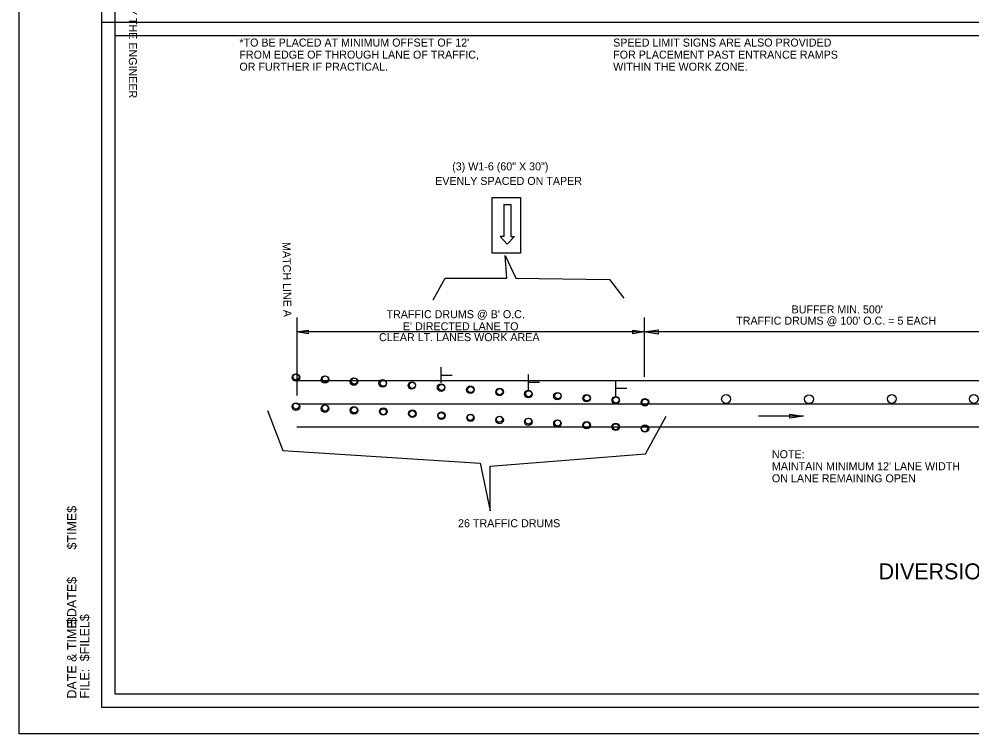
# Model space of a CAD drawing. Extents: x -500 to 213, y 382723 to 382830.
# Drawn here: x -316.3 to -244.8, y 382723.1 to 382776.7 of the extents above; entities that cross this region are included whole.
import ezdxf

# ---------------------------------------------------------------- set-up
doc = ezdxf.new("R2010")
doc.units = 0
for name, color, linetype in [('Default', 7, 'Continuous'), ('R_Border', 7, 'Continuous'), ('R_Border Notes', 7, 'Continuous'), ('R_Border Plan-Plan', 7, 'Continuous'), ('R_No Plot', 7, 'Continuous')]:
    doc.layers.add(name, color=color, linetype=linetype)

msp = doc.modelspace()

# ---------------------------------------------------------------- linework, layer by layer
at = {"layer": 'Default'}
for p, q in [((-279.942, 382762.819), (-279.942, 382760.429)), ((-279.942, 382762.819), (-279.41, 382762.819)), ((-279.41, 382762.819), (-279.41, 382760.429)), ((-279.942, 382760.429), (-280.208, 382760.429)), ((-280.208, 382760.429), (-279.676, 382759.846)), ((-279.676, 382759.846), (-279.144, 382760.429)), ((-279.41, 382760.429), (-279.144, 382760.429)), ((-295.463, 382754.338), (-295.463, 382748.51)), ((-269.405, 382754.338), (-269.405, 382749.91)), ((-295.482, 382753.26), (-294.613, 382753.39)), ((-269.405, 382753.26), (-295.482, 382753.26)), ((-294.613, 382753.129), (-295.482, 382753.26)), ((-295.463, 382752.815), (-295.463, 382748.51)), ((-294.613, 382753.39), (-294.613, 382753.129)), ((-270.274, 382753.129), (-270.274, 382753.39)), ((-270.274, 382753.39), (-269.405, 382753.26)), ((-269.405, 382753.26), (-270.274, 382753.129)), ((-269.405, 382753.26), (-268.374, 382753.414)), ((-238.494, 382753.26), (-269.405, 382753.26)), ((-268.374, 382753.105), (-269.405, 382753.26)), ((-268.374, 382753.414), (-268.374, 382753.105)), ((-284.623, 382749.452), (-284.623, 382750.614)), ((-284.606, 382750.03), (-283.813, 382750.03)), ((-278.082, 382748.911), (-278.082, 382750.072)), ((-295.463, 382749.623), (-268.558, 382749.623)), ((-278.065, 382749.488), (-277.272, 382749.488)), ((-271.525, 382748.459), (-271.525, 382749.621)), ((-269.385, 382749.623), (-242.492, 382749.623)), ((-271.508, 382749.037), (-270.716, 382749.037)), ((-295.463, 382747.884), (-268.181, 382747.884)), ((-269.475, 382747.884), (-242.275, 382747.884)), ((-258.486, 382746.796), (-258.486, 382747.105)), ((-258.486, 382747.105), (-257.456, 382746.951)), ((-257.456, 382746.951), (-260.835, 382746.951)), ((-257.456, 382746.951), (-258.486, 382746.796)), ((-295.463, 382746.146), (-267.839, 382746.146)), ((-269.426, 382746.146), (-241.92, 382746.146))]:
    msp.add_line(p, q, dxfattribs=at)
msp.add_lwpolyline([(-280.818, 382759.163), (-280.818, 382763.354), (-278.675, 382763.354), (-278.675, 382759.163)], close=True, dxfattribs=at)
for points in [[(-285.228, 382755.677), (-284.327, 382757.307), (-279.704, 382757.307), (-279.824, 382758.995), (-279.043, 382757.307), (-272.019, 382757.191), (-270.938, 382755.793)], [(-297.643, 382747.372), (-296.516, 382744.381), (-281.706, 382743.433), (-280.954, 382739.858), (-280.954, 382743.214), (-269.305, 382744.117), (-267.751, 382746.951)]]:
    msp.add_lwpolyline(points, dxfattribs=at)
for centre, radius in [((-295.522, 382749.848), 0.281), ((-295.521, 382749.894), 0.229), ((-295.509, 382749.893), 0.229), ((-293.348, 382749.696), 0.281), ((-293.328, 382749.735), 0.229), ((-291.175, 382749.543), 0.281), ((-291.148, 382749.578), 0.229), ((-289.027, 382749.406), 0.281), ((-288.967, 382749.42), 0.229), ((-286.833, 382749.247), 0.281), ((-286.786, 382749.262), 0.229), ((-284.639, 382749.088), 0.281), ((-284.606, 382749.105), 0.229), ((-282.445, 382748.929), 0.281), ((-282.425, 382748.947), 0.229), ((-280.251, 382748.769), 0.281), ((-280.244, 382748.79), 0.229), ((-278.103, 382748.604), 0.281), ((-278.064, 382748.632), 0.229), ((-275.916, 382748.452), 0.281), ((-275.883, 382748.475), 0.229), ((-273.729, 382748.299), 0.281), ((-273.702, 382748.317), 0.229), ((-271.542, 382748.147), 0.281), ((-263.269, 382748.237), 0.333), ((-257.055, 382748.222), 0.333), ((-250.841, 382748.243), 0.333), ((-244.693, 382748.245), 0.333), ((-295.522, 382747.659), 0.281), ((-295.521, 382747.704), 0.229), ((-295.509, 382747.703), 0.229), ((-293.348, 382747.521), 0.281), ((-293.331, 382747.562), 0.229), ((-271.522, 382748.159), 0.229), ((-269.355, 382747.995), 0.281), ((-269.353, 382748.003), 0.229), ((-269.341, 382748.002), 0.229), ((-291.175, 382747.382), 0.281), ((-291.153, 382747.421), 0.229), ((-288.972, 382747.301), 0.281), ((-288.976, 382747.28), 0.229), ((-286.792, 382747.142), 0.281), ((-286.798, 382747.139), 0.229), ((-284.611, 382746.982), 0.281), ((-284.62, 382746.999), 0.229), ((-282.431, 382746.823), 0.281), ((-282.442, 382746.858), 0.229), ((-280.251, 382746.664), 0.281), ((-280.264, 382746.717), 0.229), ((-278.103, 382746.526), 0.281), ((-278.087, 382746.576), 0.229), ((-275.916, 382746.402), 0.281), ((-275.909, 382746.435), 0.229), ((-273.729, 382746.277), 0.281), ((-273.731, 382746.294), 0.229), ((-271.542, 382746.152), 0.281), ((-271.553, 382746.153), 0.229), ((-269.355, 382746.028), 0.281), ((-269.388, 382746.013), 0.229), ((-269.375, 382746.012), 0.229)]:
    msp.add_circle(centre, radius, dxfattribs=at)
at = {"layer": 'R_Border'}
for p, q in [((-310.08, 382725.12), (-310.08, 382827.85)), ((-310.08, 382725.12), (-310.08, 382725.12)), ((-151.99, 382725.12), (-310.08, 382725.12))]:
    msp.add_line(p, q, dxfattribs=at)
at = {"layer": 'R_Border Plan-Plan'}
msp.add_line((-310.08, 382776.485), (-151.99, 382776.485), dxfattribs=at)
at = {"layer": 'R_No Plot'}
for points in [[(-316.283, 382829.798), (-149.613, 382829.798), (-149.613, 382723.129), (-316.283, 382723.129)], [(-309.08, 382826.85), (-184.31, 382826.85), (-184.31, 382821.91), (-175.54, 382821.91), (-163.49, 382821.91), (-163.49, 382810.744), (-152.99, 382810.744), (-152.99, 382726.12), (-309.08, 382726.12)], [(-309.08, 382775.485), (-152.99, 382775.485), (-152.99, 382726.12), (-309.08, 382726.12)]]:
    msp.add_lwpolyline(points, close=True, dxfattribs=at)

# ---------------------------------------------------------------- texts
at = {"layer": 'Default'}
for s, rotation, p in [('TO BE USED IF AND WHERE DIRECTED BY THE ENGINEER', 270, (-308.048, 382793.562)), ("*TO BE PLACED AT MINIMUM OFFSET OF 12'", 360, (-299.763, 382774.657)), ('FROM EDGE OF THROUGH LANE OF TRAFFIC,', 360, (-299.763, 382773.752)), ('OR FURTHER IF PRACTICAL.', 360, (-299.763, 382772.847)), ('(3) W1-6 (60" X 30")', 0.00754, (-283.808, 382765.374)), ('EVENLY SPACED ON TAPER', 0.00754, (-285.086, 382764.282)), ('MATCH LINE A', 270.80593, (-296.532, 382760))]:
    msp.add_text(s, height=0.6, rotation=rotation, dxfattribs=at).set_placement(p)
for s, height, p in [('SPEED LIMIT SIGNS ARE ALSO PROVIDED', 0.6, (-271.736, 382774.657)), ('FOR PLACEMENT PAST ENTRANCE RAMPS ', 0.6, (-271.736, 382773.752)), ('WITHIN THE WORK ZONE.', 0.6, (-271.736, 382772.847)), ("TRAFFIC DRUMS @ B' O.C.", 0.6, (-288.731, 382754.294)), ("BUFFER MIN. 500'", 0.6, (-258.358, 382754.653)), ("TRAFFIC DRUMS @ 100' O.C. = 5 EACH", 0.6, (-262.512, 382753.81)), ("E' DIRECTED LANE TO", 0.6, (-287.503, 382753.387)), ('CLEAR LT. LANES WORK AREA', 0.6, (-289.294, 382752.574)), ('NOTE:', 0.6, (-259.835, 382743.799)), ("MAINTAIN MINIMUM 12' LANE WIDTH", 0.6, (-259.835, 382742.895)), ('ON LANE REMAINING OPEN', 0.6, (-259.835, 382741.99)), ('26 TRAFFIC DRUMS', 0.6, (-283.368, 382738.624)), ('DIVERSION FOR LT. LANE WORK ZONE', 1.2, (-251.831, 382734.716))]:
    msp.add_text(s, height=height, dxfattribs=at).set_placement(p)
at = {"layer": 'R_Border Notes'}
for s, height, p in [('$TIME$', 0.6984, (-311.98, 382736.956)), ('$DATE$', 0.6984, (-311.98, 382731.368)), ('$FILEL$', 0.6984, (-311.02, 382728.575)), ('DATE & TIME:', 0.69839, (-311.98, 382725.781)), ('FILE: ', 0.6984, (-311.02, 382725.781))]:
    msp.add_text(s, height=height, rotation=90, dxfattribs=at).set_placement(p)

doc.saveas('drawing.dxf')
